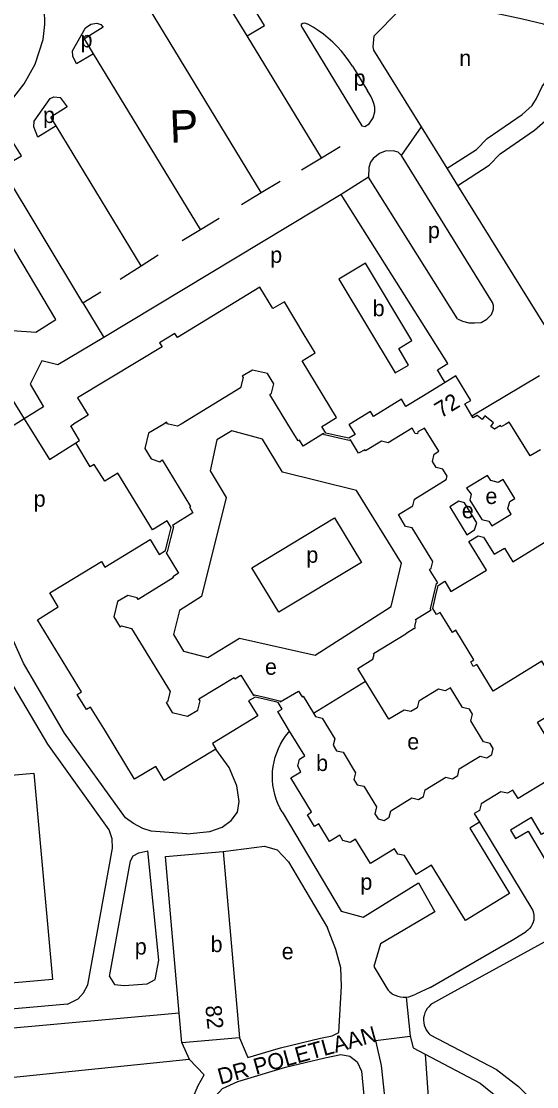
# Model space of a CAD drawing. Extents: x 158142 to 159655, y 385262 to 387204.
# Drawn here: x 158594.4 to 158722.6, y 386585.1 to 386850.2 of the extents above; entities that cross this region are included whole.
import ezdxf

# ---------------------------------------------------------------- set-up
doc = ezdxf.new("R2010")
doc.units = 0
for name, color, linetype in [('BLT_Basislijn', 7, 'Continuous'), ('BLT_Bebouwing', 7, 'Continuous'), ('BLT_Centroide', 7, 'Continuous'), ('BLT_Huisnummer', 7, 'Continuous'), ('BLT_Straatnaam_verkleind', 7, 'Continuous'), ('BLT_Tekst_parkeren', 7, 'Continuous'), ('BLT_Vlakafsluiter', 7, 'Continuous')]:
    doc.layers.add(name, color=color, linetype=linetype)

msp = doc.modelspace()

# ---------------------------------------------------------------- linework, layer by layer
at = {"layer": 'BLT_Basislijn'}
for p, q in [((158654.05, 386807.61), (158626.22, 386853.36)), ((158612.33, 386842.15), (158610.06, 386845.88)), ((158669, 386816.28), (158650.56, 386846.6)), ((158638.92, 386798.45), (158612.33, 386842.15)), ((158676.72, 386839.09), (158680.49, 386832.9)), ((158603.01, 386824.19), (158601.69, 386826.36)), ((158624.17, 386789.4), (158603.01, 386824.19)), ((158669, 386816.28), (158673.69, 386819.09)), ((158664.05, 386813.31), (158669, 386816.28)), ((158654.05, 386807.61), (158658.74, 386810.42)), ((158775.77, 386691.97), (158702.96, 386809.4)), ((158673.96, 386807.13), (158614.92, 386771.55)), ((158649.1, 386804.64), (158654.05, 386807.61)), ((158638.92, 386798.45), (158643.56, 386801.26)), ((158634.41, 386795.72), (158638.92, 386798.45)), ((158624.17, 386789.4), (158628.39, 386792.1)), ((158618.99, 386786.08), (158624.17, 386789.4)), ((158609.67, 386780.2), (158614.17, 386782.94)), ((158609.67, 386780.2), (158614.92, 386771.55)), ((158699.82, 386760.37), (158699.26, 386761.27)), ((158706.46, 386752.08), (158723.25, 386762.04)), ((158667.04, 386678.07), (158679.99, 386686.03)), ((158646.07, 386664.49), (158642.77, 386669.11)), ((158708.34, 386650.9), (158721.6, 386628.89)), ((158610.87, 386610.43), (158617.01, 386644.4)), ((158644.57, 386643.58), (158654.83, 386644.95)), ((158660.79, 386641.05), (158670.54, 386624.61)), ((158716.87, 386621.76), (158719.95, 386623.69)), ((158696.11, 386609.79), (158716.87, 386621.76)), ((158696.11, 386609.79), (158692.53, 386608.12)), ((158690.06, 386607.38), (158691.08, 386597.64)), ((158648.61, 386597.21), (158650.72, 386592.32)), ((158634.29, 386595.96), (158636.14, 386591.88)), ((158555.4, 386583.71), (158636.14, 386591.88)), ((158636.14, 386591.88), (158639.85, 386588.02))]:
    msp.add_line(p, q, dxfattribs=at)
for points in [[(158588.55, 386827.21), (158591.7, 386830.27), (158595.11, 386834.66), (158597.78, 386839.54), (158599.8, 386845.67), (158600.25, 386849.45), (158600.15, 386853.26), (158599.44, 386857.59), (158598, 386861.47), (158594.4, 386868.25), (158591.12, 386873.15), (158587.7, 386877.49), (158583.18, 386881.78), (158579.53, 386884.75), (158576.62, 386886.78), (158574.2, 386888.04)], [(158650.56, 386846.6), (158645.11, 386855.54), (158640.56, 386852.77), (158636.49, 386859.45), (158636.56, 386860.12), (158637.37, 386860.61), (158638.94, 386860.64)], [(158650.56, 386846.6), (158654.84, 386849.2), (158650.86, 386855.74)], [(158731.6, 386841.96), (158728.58, 386846.31), (158726.56, 386848.18), (158724.3, 386849.49), (158719.03, 386850.79), (158696.95, 386855.61), (158693.92, 386855.92), (158692.49, 386855.5), (158688.28, 386852.84)], [(158693.92, 386823.99), (158682.07, 386843.09), (158681.86, 386843.92), (158682.12, 386846.62), (158688.28, 386852.84)], [(158612.33, 386842.15), (158608.05, 386839.62), (158607.15, 386841.59), (158607.1, 386842.87), (158610.37, 386848.59), (158611.64, 386849.5), (158613.18, 386849.75), (158614.18, 386849.48), (158614.76, 386848.74), (158610.06, 386845.88)], [(158676.72, 386839.09), (158675.87, 386840.38), (158674.96, 386841.62), (158673.98, 386842.81), (158672.94, 386843.95), (158671.85, 386845.03), (158670.7, 386846.06), (158669.5, 386847.02), (158668.25, 386847.92), (158666.95, 386848.76), (158665.62, 386849.52), (158665.59, 386849.53), (158664.87, 386849.79), (158664.36, 386849.73), (158664.01, 386849.42), (158664.02, 386849.14), (158664.28, 386848.53)], [(158664.28, 386848.53), (158679.07, 386824.23), (158679.81, 386824.07), (158680.92, 386824.75), (158681.89, 386826.19), (158682.3, 386827.68), (158682.31, 386828.85)], [(158700.33, 386813.65), (158707.59, 386818.35), (158710.25, 386821.06), (158718.92, 386827.06), (158721.46, 386829.32), (158722.54, 386831.03), (158723.97, 386834.01), (158725.96, 386836.75), (158730.43, 386841.33), (158731.6, 386841.96)], [(158702.96, 386809.4), (158710.77, 386814.45), (158713.48, 386817.21), (158722.02, 386823.12), (158725.31, 386826.06), (158726.92, 386828.6), (158728.28, 386831.44), (158729.79, 386833.52), (158733.48, 386837.29), (158734.47, 386837.83)], [(158682.31, 386828.85), (158682.05, 386829.78), (158681.71, 386830.69), (158681.3, 386831.57), (158680.82, 386832.4), (158680.49, 386832.9)], [(158603.01, 386824.19), (158598.49, 386821.43), (158597.44, 386823.95), (158597.56, 386825.37), (158601.57, 386830.99), (158602.49, 386831.42), (158604.04, 386831.26), (158605.77, 386828.93), (158601.69, 386826.36)], [(158700.33, 386813.65), (158693.92, 386823.99)], [(158609.67, 386780.2), (158589.44, 386813.85), (158594.37, 386816.75), (158592.35, 386820.08), (158590.98, 386819.85)], [(158688.96, 386816.8), (158688.1, 386817.65), (158686.83, 386818.01), (158684.87, 386817.95), (158683.44, 386817.32), (158681.89, 386816.12), (158681.25, 386815.14), (158680.79, 386813.87), (158680.69, 386811.46)], [(158702.91, 386776.17), (158704.09, 386775.57), (158705.67, 386775.17), (158707.08, 386775.15), (158708.72, 386775.3), (158710.15, 386776.09), (158711.35, 386777.27), (158711.7, 386778.08), (158711.85, 386778.67), (158711.82, 386779.53), (158711.61, 386780.27), (158688.96, 386816.8)], [(158568.03, 386803.25), (158586.12, 386773.69), (158597.99, 386772.83), (158602.92, 386776.03), (158581.18, 386812.61)], [(158702.91, 386776.17), (158680.69, 386811.46)], [(158702.96, 386809.4), (158700.33, 386813.65)], [(158699.26, 386761.27), (158697.89, 386763.45), (158700.43, 386765.08), (158673.96, 386807.13)], [(158614.92, 386771.55), (158603.47, 386764.7), (158599.47, 386765.75), (158596.55, 386759.91), (158599.84, 386754.27), (158595.06, 386751.27)], [(158595.06, 386751.27), (158601.37, 386741.2), (158607.9, 386745.29)], [(158646.77, 386748.32), (158643.02, 386746.03), (158641.35, 386738.39), (158645.3, 386731.72), (158639.2, 386707.04), (158633.69, 386703.57), (158632.18, 386697.6), (158634.67, 386693.47), (158640.75, 386691.89), (158648.66, 386696.74), (158667.43, 386692.45), (158686.33, 386704.6), (158688.92, 386715.36), (158677.75, 386733.43), (158659.31, 386738), (158654.36, 386746.25), (158646.77, 386748.32)], [(158620.27, 386651.95), (158605.13, 386673.03), (158594.88, 386690.47), (158583.1, 386716.52), (158576.75, 386739.81)], [(158617.01, 386644.4), (158616.96, 386646.73), (158616.24, 386648.98), (158600.94, 386670.3), (158590.44, 386688.17), (158585.85, 386698.3)], [(158659.24, 386653.46), (158658.68, 386654.49), (158658.18, 386655.55), (158657.77, 386656.65), (158657.42, 386657.77), (158657.16, 386658.92), (158656.97, 386660.08), (158656.86, 386661.24), (158656.84, 386662.42), (158656.89, 386663.59), (158657.02, 386664.76), (158657.23, 386665.91), (158657.52, 386667.05), (158657.89, 386668.17), (158658.33, 386669.25), (158658.84, 386670.31), (158659.43, 386671.33), (158660.08, 386672.3), (158660.8, 386673.23), (158661.1, 386673.59)], [(158641.23, 386648.59), (158644.31, 386649.65), (158646.53, 386651.29), (158648.12, 386653.39), (158648.53, 386656.01), (158647.96, 386659.91), (158646.07, 386664.49)], [(158659.24, 386653.46), (158673.92, 386628.72), (158679.37, 386627.26), (158693.2, 386635.81), (158697.24, 386628.59), (158683.71, 386620.66), (158682.07, 386614.97), (158685.28, 386609.57)], [(158783.34, 386653.33), (158700.4, 386607.86), (158696.69, 386605.76)], [(158635.56, 386648.02), (158626.66, 386648.69), (158624.62, 386649.31), (158622.26, 386650.55), (158620.27, 386651.95)], [(158635.56, 386648.02), (158641.23, 386648.59)], [(158654.83, 386644.95), (158658.01, 386643.98), (158660.79, 386641.05)], [(158616.31, 386612.45), (158621.53, 386641.3), (158622.18, 386642.55), (158623.6, 386643.31), (158625.86, 386643.74)], [(158628.61, 386616.58), (158625.86, 386643.74)], [(158721.6, 386628.89), (158721.78, 386628.32), (158721.87, 386627.74), (158721.89, 386627.15), (158721.82, 386626.56), (158721.68, 386625.98), (158721.46, 386625.43), (158721.17, 386624.92), (158720.81, 386624.45), (158720.39, 386624.03), (158719.95, 386623.69)], [(158650.72, 386592.32), (158658.81, 386594.73), (158668.75, 386597.11), (158671.67, 386597.75), (158673.34, 386598.58), (158674.04, 386610.12), (158673.87, 386614.67), (158672.57, 386619.17), (158670.54, 386624.61)], [(158616.31, 386612.45), (158617.54, 386610.5), (158619.96, 386610.21), (158625.66, 386610.7), (158627.67, 386611.77), (158628.61, 386616.58)], [(158605.85, 386605.61), (158608.49, 386606.94), (158609.82, 386608.44), (158610.87, 386610.43)], [(158685.28, 386609.57), (158685.63, 386609.08), (158686.04, 386608.64), (158686.51, 386608.26), (158686.73, 386608.11)], [(158686.73, 386608.11), (158687.35, 386607.82), (158688, 386607.59), (158688.68, 386607.44), (158689.37, 386607.37), (158690.06, 386607.38)], [(158690.06, 386607.38), (158690.74, 386607.47), (158691.41, 386607.64), (158692.06, 386607.89), (158692.53, 386608.12)], [(158605.85, 386605.61), (158520.48, 386598.05), (158519.86, 386604.13)], [(158696.69, 386605.76), (158696.18, 386605.4), (158695.73, 386604.98), (158695.33, 386604.5), (158695, 386603.98), (158694.74, 386603.42), (158694.55, 386602.82), (158694.44, 386602.21), (158694.41, 386601.59), (158694.46, 386600.97), (158694.58, 386600.37), (158694.79, 386599.78), (158695.07, 386599.23), (158695.41, 386598.71), (158695.82, 386598.24), (158696.08, 386598.01)], [(158633.64, 386603.39), (158452.87, 386587.05), (158448.01, 386587.83), (158444.32, 386590.32), (158441.8, 386593.78), (158440.82, 386598.65)], [(158682.46, 386596.54), (158683.89, 386590.31), (158684.67, 386582.6), (158683.41, 386576.63), (158682.28, 386573.18), (158679.27, 386571.18), (158673.14, 386570.81)], [(158682.46, 386596.54), (158691.08, 386597.64)], [(158691.08, 386597.64), (158691.88, 386594.76), (158694.85, 386593.18)], [(158696.08, 386598.01), (158712.54, 386589.37), (158718.01, 386585.14), (158723.17, 386579.86), (158730.26, 386569.56), (158741.33, 386549.4)], [(158694.85, 386593.18), (158698.92, 386534.83), (158608.08, 386525.63)], [(158694.85, 386593.18), (158708.52, 386585.9), (158712.94, 386582.4), (158718.17, 386577.51), (158721.5, 386572.99), (158725.33, 386567.01), (158739.93, 386538.93)], [(158635.79, 386576.3), (158636.16, 386579.46), (158636.96, 386582.06), (158638.38, 386585.39), (158639.85, 386588.02)]]:
    msp.add_lwpolyline(points, dxfattribs=at)
for points in [[(158651.69, 386714.2), (158672.27, 386726.65), (158678.95, 386715.55), (158658.43, 386703.15)], [(158562.78, 386659.99), (158597.51, 386663.1), (158602.1, 386611.75), (158567.37, 386608.64)], [(158730.85, 386657.75), (158725.64, 386654.65), (158728.16, 386650.42), (158723.8, 386647.82), (158721.29, 386652.03), (158716.07, 386648.92), (158717.32, 386646.82), (158720.43, 386648.68), (158730.02, 386632.57), (158726.88, 386630.7), (158727.87, 386629.03), (158742.68, 386637.11), (158740.94, 386640.01), (158738.48, 386638.53), (158729.22, 386653.98), (158732.1, 386655.63)], [(158641.87, 386578.76), (158641.73, 386579.33), (158641.87, 386580.83), (158642.65, 386582.67), (158644.41, 386584.64), (158648.2, 386586.36), (158660.11, 386589.9), (158669.87, 386592.23), (158673.82, 386593.1), (158676.05, 386592.69), (158677.89, 386591.29), (158679, 386588.95), (158679.61, 386582.87), (158678.57, 386577.93), (158678.06, 386576.38), (158677.63, 386576.09), (158662.57, 386575.19), (158650.03, 386575.39), (158644.95, 386576.29), (158642.77, 386577.71)]]:
    msp.add_lwpolyline(points, close=True, dxfattribs=at)
at = {"layer": 'BLT_Bebouwing'}
for p, q in [((158706.46, 386752.08), (158704.7, 386754.99)), ((158606.68, 386749.58), (158607.37, 386750)), ((158630.24, 386642.33), (158644.57, 386643.58)), ((158633.64, 386603.39), (158630.24, 386642.33)), ((158644.57, 386643.58), (158648.61, 386597.21)), ((158634.29, 386595.96), (158633.64, 386603.39)), ((158648.61, 386597.21), (158634.29, 386595.96))]:
    msp.add_line(p, q, dxfattribs=at)
for points in [[(158680, 386790.03), (158673.39, 386786.05), (158687.4, 386762.71), (158690.71, 386764.69), (158688.27, 386768.76), (158691.55, 386770.8)], [(158710.37, 386737.21), (158705.13, 386734.02), (158706.29, 386732.54), (158705.96, 386731.07), (158708.89, 386726.25), (158710.65, 386725.8), (158711.42, 386724.66), (158716.24, 386727.6), (158715.38, 386729.01), (158715.85, 386730.7), (158717.14, 386731.48), (158714.25, 386736.23), (158712.99, 386735.46), (158711.15, 386735.92)], [(158704.63, 386730.4), (158703.17, 386730.77), (158700.93, 386729.41), (158705.18, 386722.44), (158707.12, 386723.63), (158707.69, 386725.37)]]:
    msp.add_lwpolyline(points, close=True, dxfattribs=at)
for points in [[(158673.11, 386747.06), (158670.1, 386747.75), (158669.11, 386749.37), (158670.15, 386750), (158672.78, 386751.6), (158664.21, 386765.71), (158667.49, 386767.72), (158664.76, 386772.2), (158659.8, 386780.45), (158656.95, 386778.72), (158653.7, 386784.05), (158639.18, 386775.19), (158633.18, 386771.55), (158632.56, 386772.54), (158628.76, 386770.22), (158629.36, 386769.21), (158623.38, 386765.55), (158608.37, 386756.55), (158610.97, 386752.22), (158607.37, 386750)], [(158588.92, 386761.1), (158595.06, 386751.27)], [(158672.98, 386746.54), (158669.77, 386747.27), (158669.57, 386747.62), (158664.45, 386744.51), (158663.54, 386745.99), (158663.24, 386745.81), (158660.68, 386750), (158656.18, 386757.38), (158656.61, 386757.66), (158657.18, 386759.99), (158655.61, 386762.55), (158651.85, 386763.43), (158649.32, 386761.88), (158649.57, 386761.58), (158648.92, 386759.04), (158634.15, 386750), (158633.23, 386749.44), (158630.98, 386750), (158630.71, 386750.07), (158630.52, 386750.43), (158629.8, 386750), (158626.03, 386747.71), (158625.08, 386743.94), (158626.65, 386741.36), (158628.85, 386740.57), (158629.43, 386741.05), (158636.49, 386729.51), (158636.21, 386729.35), (158637.05, 386727.87), (158631.99, 386724.72), (158632.2, 386724.41), (158631.48, 386721.49)], [(158702.45, 386761.98), (158699.82, 386760.37)], [(158704.7, 386754.99), (158706.18, 386755.89), (158702.45, 386761.98)], [(158699.82, 386760.37), (158693.97, 386756.8), (158690.02, 386754.39), (158688.98, 386756.15), (158681.98, 386751.89), (158681.23, 386753.15), (158676.09, 386750), (158675.87, 386749.87), (158677.41, 386747.38), (158675.83, 386746.44), (158673.11, 386747.06)], [(158595.06, 386751.27), (158583.73, 386744.18)], [(158723.49, 386743.57), (158720.91, 386742.05), (158716.02, 386750), (158715.73, 386750.49), (158714.93, 386750), (158713.75, 386749.29), (158713.56, 386749.6), (158712.06, 386748.7), (158711.14, 386749.42), (158711.84, 386750.32), (158709.68, 386752.01), (158708.98, 386751.11), (158707.77, 386752.11), (158706.81, 386751.51), (158706.81, 386751.51), (158706.46, 386752.08)], [(158607.9, 386745.29), (158608.87, 386745.89), (158606.68, 386749.58)], [(158696.91, 386707.18), (158697.68, 386710.3), (158697.95, 386710.48), (158695.94, 386713.82), (158696.36, 386714.1), (158696.76, 386715.75), (158691.62, 386724.16), (158689.95, 386724.53), (158688.19, 386727.49), (158691.74, 386729.66), (158692.16, 386731.3), (158700.08, 386736.17), (158700.3, 386737), (158699.23, 386738.79), (158697.58, 386739.16), (158696.63, 386740.7), (158697.08, 386742.5), (158698.23, 386743.21), (158694.63, 386749.01), (158693.02, 386748.02), (158692.91, 386747.55), (158692.33, 386747.64), (158691.58, 386748.99), (158685.63, 386745.36), (158683.98, 386745.73), (158679.96, 386743.3), (158679.78, 386743.58), (158678.28, 386742.71), (158676.26, 386746.03), (158675.96, 386745.86), (158672.98, 386746.54)], [(158630.96, 386721.61), (158631.61, 386724.26), (158630.66, 386725.89), (158627, 386723.66), (158618.34, 386737.73), (158615.12, 386735.75), (158612.47, 386739.95), (158611.51, 386739.36), (158607.9, 386745.29)], [(158605.03, 386710.13), (158614.29, 386715.77), (158615.12, 386714.37), (158626.41, 386721.25), (158628.65, 386717.56), (158630.21, 386718.55), (158630.96, 386721.61)], [(158631.48, 386721.49), (158630.66, 386718.19), (158630.36, 386717.98), (158633.48, 386712.9), (158632.02, 386711.97), (158632.17, 386711.7), (158623.43, 386706.36), (158623.18, 386706.77), (158620.82, 386707.36), (158618.25, 386705.8), (158617.36, 386702.03), (158618.92, 386699.48), (158619.26, 386699.74), (158621.8, 386699.08), (158631.39, 386683.42), (158630.74, 386680.88), (158630.4, 386680.66), (158631.93, 386678.16), (158635.74, 386677.25), (158638.27, 386678.78), (158638.85, 386681.13), (158638.56, 386681.56), (158647.29, 386686.88), (158647.48, 386686.61), (158648.96, 386687.51), (158652.09, 386682.42), (158652.38, 386682.6), (158655.26, 386681.92)], [(158697.42, 386707.06), (158698.08, 386709.85), (158699.7, 386710.86), (158701.25, 386708.28), (158710.07, 386713.64), (158705.71, 386720.79), (158708.05, 386722.16), (158709.37, 386721.86), (158711.97, 386717.59), (158714.53, 386719.1), (158716.61, 386715.72), (158725.52, 386721.16)], [(158642.77, 386669.11), (158633.54, 386663.48), (158629.93, 386661.27), (158627.79, 386664.77), (158622.54, 386661.58), (158615.28, 386673.55), (158611.61, 386679.54), (158610.56, 386678.94), (158608.29, 386682.69), (158609.3, 386683.34), (158605.65, 386689.32), (158598.35, 386701.27), (158603.57, 386704.46), (158601.43, 386707.96), (158605.03, 386710.13)], [(158692.1, 386699.13), (158692.4, 386699.28), (158692.22, 386699.58), (158692.56, 386701.04), (158692.41, 386701.31), (158696.29, 386703.73), (158696.13, 386704.04), (158696.91, 386707.18)], [(158707.98, 386689.64), (158707.66, 386690.16), (158706.79, 386689.63), (158706.16, 386690.8), (158706.97, 386691.27), (158702.48, 386698.66), (158701.6, 386698.13), (158698.58, 386703.06), (158697.67, 386702.56), (158696.72, 386704.12), (158697.42, 386707.06)], [(158679.99, 386686.03), (158678.07, 386689.16), (158681.82, 386691.44), (158682.11, 386692.62), (158681.95, 386692.88), (158689.99, 386697.78)], [(158692.1, 386699.13), (158689.99, 386697.78)], [(158725.61, 386671.11), (158722.75, 386675.8), (158730.29, 386680.38), (158723.84, 386690.97), (158711.71, 386683.51), (158707.98, 386689.64)], [(158672.76, 386668.68), (158674.41, 386668.3), (158677.53, 386663.17), (158677.12, 386661.51), (158677.9, 386660.23), (158679.58, 386659.83), (158682.71, 386654.7), (158682.3, 386653), (158683.1, 386651.73), (158684.61, 386651.35), (158685.91, 386652.16), (158686.29, 386653.75), (158691.54, 386656.96), (158693.14, 386656.54), (158694.43, 386657.32), (158694.81, 386658.95), (158699.98, 386662.13), (158701.63, 386661.73), (158702.92, 386662.51), (158703.3, 386664.18), (158708.5, 386667.32), (158710.16, 386666.93), (158711.43, 386667.71), (158711.78, 386669.23), (158711, 386670.52), (158709.37, 386670.91), (158706.19, 386676.09), (158706.61, 386677.75), (158705.83, 386679.03), (158704.15, 386679.41), (158701.17, 386684.37), (158699.8, 386683.58), (158698.15, 386683.98), (158693.22, 386681), (158692.82, 386679.35), (158691.28, 386678.41), (158689.63, 386678.8), (158685.83, 386676.5), (158679.99, 386686.03)], [(158655.15, 386681.42), (158652.54, 386682.03), (158650.91, 386681.08), (158653.19, 386677.37), (158641.91, 386670.48), (158642.77, 386669.11)], [(158661.1, 386673.59), (158658.16, 386678.42), (158659.24, 386679.05), (158658.23, 386680.69), (158655.15, 386681.42)], [(158655.26, 386681.92), (158658.57, 386681.13), (158658.78, 386680.82), (158663.3, 386683.55), (158664.19, 386682.08), (158664.48, 386682.25), (158667.04, 386678.07)], [(158667.04, 386678.07), (158667.56, 386677.22), (158669.23, 386676.79), (158672.38, 386671.64), (158671.96, 386670.03), (158672.76, 386668.68)], [(158715.84, 386633.16), (158704.85, 386626.45), (158696.4, 386640.22), (158692.6, 386637.91), (158689.71, 386642.62), (158688.04, 386642.98), (158687.21, 386644.23), (158681.2, 386640.63), (158677.49, 386646.69), (158676.16, 386645.86), (158674.35, 386646.32), (158673.56, 386647.64), (158671.05, 386646.11), (158668.36, 386650.5), (158667.29, 386649.86), (158665.53, 386652.75), (158666.58, 386653.45), (158661.41, 386661.95), (158663.9, 386663.45), (158663.12, 386664.82), (158663.55, 386666.62), (158664.88, 386667.4), (158661.1, 386673.59)], [(158725.33, 386661.29), (158717.94, 386656.78), (158716.61, 386658.87), (158715.3, 386658.1), (158713.66, 386658.48), (158708.76, 386655.49), (158708.35, 386653.84), (158707.05, 386653.03), (158708.34, 386650.9)], [(158708.34, 386650.9), (158705.91, 386649.4), (158715.84, 386633.16)]]:
    msp.add_lwpolyline(points, dxfattribs=at)
at = {"layer": 'BLT_Vlakafsluiter'}
for p, q in [((158688.96, 386816.8), (158693.92, 386823.99)), ((158680.69, 386811.46), (158673.96, 386807.13))]:
    msp.add_line(p, q, dxfattribs=at)

# ---------------------------------------------------------------- texts
at = {"layer": 'BLT_Centroide'}
for s, p in [('p', (158609.1, 386843.75)), ('n', (158703.31, 386839.1)), ('p', (158677.02, 386834.17)), ('p', (158599.77, 386824.92)), ('p', (158695.51, 386796.24)), ('p', (158656.28, 386790.11)), ('b', (158681.77, 386776.84)), ('p', (158597.44, 386729.42)), ('e', (158709.82, 386730.09)), ('e', (158703.95, 386726.54)), ('p', (158665.27, 386715.47)), ('e', (158654.98, 386687.59)), ('e', (158690.37, 386668.98)), ('b', (158667.7, 386663.64)), ('p', (158678.71, 386634.07)), ('p', (158622.6, 386617.95)), ('b', (158641.45, 386618.56)), ('e', (158659.14, 386616.77))]:
    msp.add_text(s, height=4, dxfattribs=at).set_placement(p)
at = {"layer": 'BLT_Huisnummer'}
for s, rotation, p in [('72', 31.4443, (158698.74, 386751.37)), ('82', 275.7842, (158640.13, 386605.14))]:
    msp.add_text(s, height=4, rotation=rotation, dxfattribs=at).set_placement(p)
at = {"layer": 'BLT_Straatnaam_verkleind'}
msp.add_text('DR POLETLAAN', height=4, rotation=15.407, dxfattribs=at).set_placement((158643.85, 386585.56))
at = {"layer": 'BLT_Tekst_parkeren'}
msp.add_text('P', height=8, rotation=2.473, dxfattribs=at).set_placement((158631.43, 386820))

doc.saveas('drawing.dxf')
